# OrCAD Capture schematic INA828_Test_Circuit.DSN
size A; title: INA828 50-µV Offset, 7-nV/vHz Noise, Low-Power,; rev: 1.4; note: Datasheet:SBOS792A   EVM: N/A
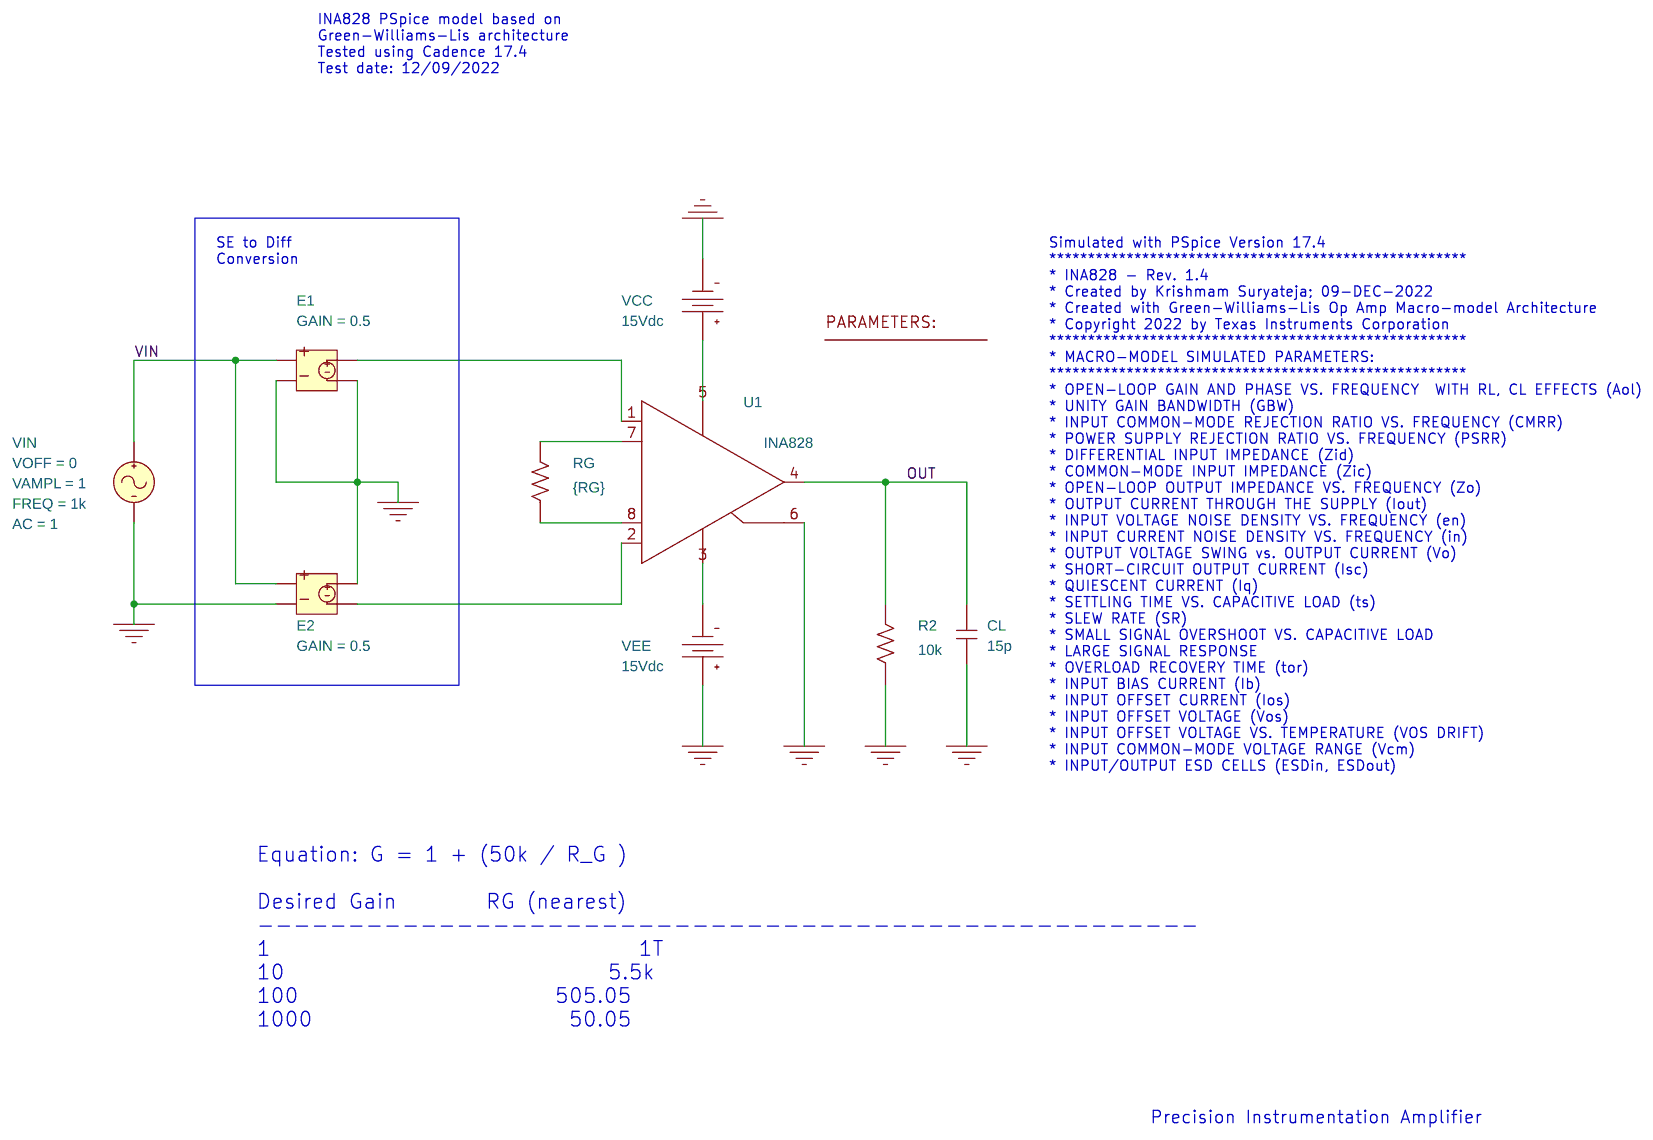
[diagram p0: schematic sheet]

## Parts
1  PARAM
CL  15p  [RAD/CK05]
E1  E
E2  E
R2  10k  [AXRC05]
RG  {RG}  [AXRC05]
U1  INA828
VCC  VDC
VEE  VDC
VIN  VSIN

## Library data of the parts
1 = PARAM: RG: 1T
CL = C
E1 E2 = E: GAIN: 0.5
R2 RG = R
U1 = INA828
VCC VEE = VDC: DC: 15Vdc
VIN = VSIN: AC: 1; FREQ: 1k; VAMPL: 1; VOFF: 0

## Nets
VIN: E1.1 E2.1 VIN.1(+)
0: CL.1 E1.2 E1.4 E2.2 E2.3 R2.1 U1.6(REF) VCC.1(-) VEE.0(+) VIN.2(-)
OUT: CL.2 R2.2 U1.4(OUT)
N16988: RG.2 U1.7(RG+)
N17159: RG.1 U1.8(RG-)
N24931: U1.5(V+) VCC.0(+)
N31654: U1.3(V-) VEE.1(-)
N32560: E1.3 U1.1(+)
N32567: E2.4 U1.2(-)

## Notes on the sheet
- INA828 PSpice model based on
  Green-Williams-Lis architecture
  Tested using Cadence 17.4
  Test date: 12/09/2022
- SE to Diff
  Conversion
- Simulated with PSpice Version 17.4
  ******************************************************
  * INA828 - Rev. 1.4
  * Created by Krishmam Suryateja; 09-DEC-2022
  * Created with Green-Williams-Lis Op Amp Macro-model Architecture
  * Copyright 2022 by Texas Instruments Corporation
  ******************************************************
  * MACRO-MODEL SIMULATED PARAMETERS:
  ******************************************************
  * OPEN-LOOP GAIN AND PHASE VS. FREQUENCY  WITH RL, CL EFFECTS (Aol)
  * UNITY GAIN BANDWIDTH (GBW)
  * INPUT COMMON-MODE REJECTION RATIO VS. FREQUENCY (CMRR)
  * POWER SUPPLY REJECTION RATIO VS. FREQUENCY (PSRR)
  * DIFFERENTIAL INPUT IMPEDANCE (Zid)
  * COMMON-MODE INPUT IMPEDANCE (Zic)
  * OPEN-LOOP OUTPUT IMPEDANCE VS. FREQUENCY (Zo)
  * OUTPUT CURRENT THROUGH THE SUPPLY (Iout)
  * INPUT VOLTAGE NOISE DENSITY VS. FREQUENCY (en)
  * INPUT CURRENT NOISE DENSITY VS. FREQUENCY (in)
  * OUTPUT VOLTAGE SWING vs. OUTPUT CURRENT (Vo)
  * SHORT-CIRCUIT OUTPUT CURRENT (Isc)
  * QUIESCENT CURRENT (Iq)
  * SETTLING TIME VS. CAPACITIVE LOAD (ts)
  * SLEW RATE (SR)
  * SMALL SIGNAL OVERSHOOT VS. CAPACITIVE LOAD
  * LARGE SIGNAL RESPONSE
  * OVERLOAD RECOVERY TIME (tor)
  * INPUT BIAS CURRENT (Ib)
  * INPUT OFFSET CURRENT (Ios)
  * INPUT OFFSET VOLTAGE (Vos)
  * INPUT OFFSET VOLTAGE VS. TEMPERATURE (VOS DRIFT)
  * INPUT COMMON-MODE VOLTAGE RANGE (Vcm)
  * INPUT/OUTPUT ESD CELLS (ESDin, ESDout)
- Equation: G = 1 + (50k / R_G )
  Desired Gain        RG (nearest)
  ----------------------------------------------------
  1                                 1T
  10                             5.5k
  100                       505.05
  1000                       50.05
- Precision Instrumentation Amplifier
